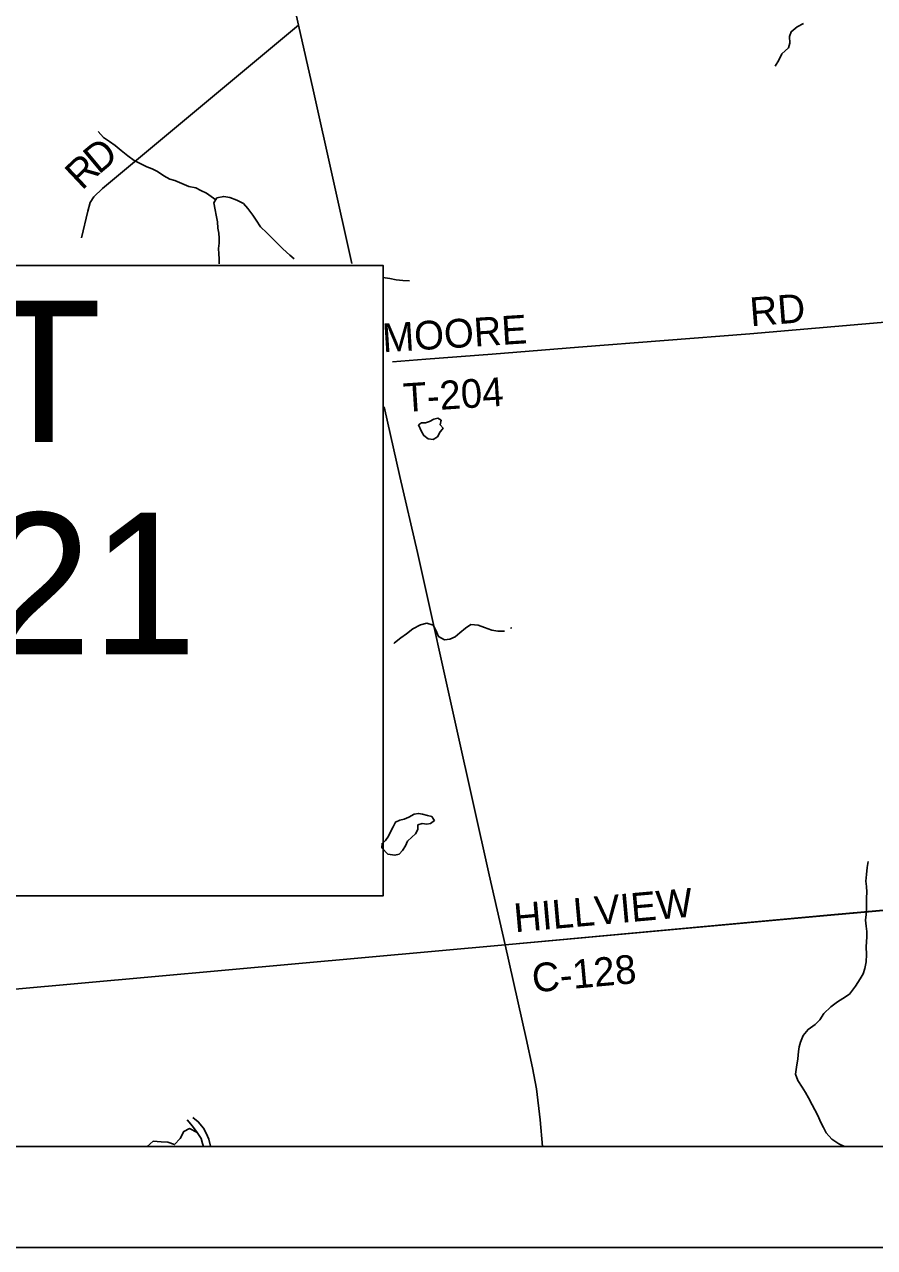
# Model space of a CAD drawing. Extents: x 0 to 34, y 0 to 22.
# Drawn here: x 6.665 to 7.506, y 14 to 15.21 of the extents above; entities that cross this region are included whole.
import ezdxf

# ---------------------------------------------------------------- set-up
doc = ezdxf.new("R2010")
doc.units = 0
for name, color, linetype in [('GM_X_Corporation', 7, 'Continuous'), ('GM_X_County_Road', 7, 'Continuous'), ('GM_X_County_Road_Text', 7, 'Continuous'), ('GM_X_Minor_Lake', 7, 'Continuous'), ('GM_X_Minor_River', 7, 'Continuous'), ('GM_X_State_Route', 7, 'Continuous'), ('GM_X_Township_Road', 7, 'Continuous'), ('GM_X_Township_Road_Text', 7, 'Continuous'), ('SH_Data', 7, 'Continuous'), ('SH_Text', 7, 'Continuous')]:
    doc.layers.add(name, color=color, linetype=linetype)

msp = doc.modelspace()

# ---------------------------------------------------------------- linework, layer by layer
at = {"layer": 'GM_X_Corporation'}
msp.add_lwpolyline([(2.7052, 14.1), (8.9, 14.1), (8.9, 20.9), (3.3687, 20.9)], dxfattribs=at)
msp.add_lwpolyline([(5.0367, 14.1), (8.579, 14.1), (8.5781, 14.1185), (8.5553, 14.4065), (8.4217, 14.3956), (8.2117, 14.3797), (8.0986, 14.3711), (7.9912, 14.363), (7.8543, 14.3535), (7.661, 14.3447), (7.5929, 14.3405), (7.4631, 14.3291), (7.1407, 14.2995), (6.5134, 14.2426), (6.0344, 14.1984), (5.9982, 14.195), (5.4229, 14.1455), (5.0357, 14.1114)], close=True, dxfattribs=at)
at = {"layer": 'GM_X_County_Road'}
for points in [[(6.7214, 14.9988), (6.7276, 15.0252), (6.7301, 15.0337), (6.7336, 15.0395), (6.7423, 15.0475), (6.9363, 15.2093)], [(7.1408, 14.2993), (7.4632, 14.3289), (7.593, 14.3402), (7.6611, 14.3445), (7.8544, 14.3533), (7.9913, 14.3627)]]:
    msp.add_lwpolyline(points, dxfattribs=at)
at = {"layer": 'GM_X_Minor_Lake'}
for points in [[(7.0783, 14.8092), (7.0793, 14.8107), (7.0765, 14.814), (7.0774, 14.8183), (7.0742, 14.8204), (7.0702, 14.8193), (7.066, 14.8172), (7.0621, 14.8157), (7.0579, 14.8159), (7.055, 14.8137)], [(7.055, 14.8137), (7.0579, 14.8072), (7.0603, 14.8032), (7.0647, 14.8), (7.0696, 14.7994), (7.0738, 14.802), (7.0766, 14.8068), (7.0783, 14.8092)], [(7.07, 14.4238), (7.0682, 14.4264), (7.0638, 14.4274), (7.0591, 14.4286), (7.0549, 14.4295), (7.0506, 14.4286), (7.0456, 14.4258), (7.0407, 14.4237), (7.0367, 14.4229), (7.0324, 14.4209), (7.0299, 14.4163), (7.0276, 14.412), (7.0253, 14.4069), (7.0223, 14.4027), (7.019, 14.3997), (7.0186, 14.3953), (7.0247, 14.3891)], [(7.0247, 14.3891), (7.0317, 14.3881), (7.0358, 14.389), (7.0393, 14.3928), (7.0423, 14.3975), (7.044, 14.4021), (7.0484, 14.4058), (7.0522, 14.4092), (7.0545, 14.4136), (7.0545, 14.4181), (7.0587, 14.4196), (7.0632, 14.4189), (7.067, 14.4196), (7.0708, 14.4226), (7.07, 14.4238)]]:
    msp.add_lwpolyline(points, dxfattribs=at)
at = {"layer": 'GM_X_Minor_River'}
for points in [[(7.436, 15.2108), (7.4297, 15.2076), (7.4238, 15.2027), (7.4221, 15.198), (7.4225, 15.1915), (7.4211, 15.1868), (7.4148, 15.1809), (7.4116, 15.1747), (7.408, 15.1688)], [(6.8543, 15.0364), (6.8451, 15.0429), (6.8395, 15.0456), (6.8346, 15.0483), (6.8276, 15.0497), (6.8208, 15.0526), (6.814, 15.0556), (6.809, 15.057), (6.803, 15.0603), (6.7966, 15.0643), (6.7913, 15.067), (6.786, 15.0691), (6.7796, 15.0725), (6.7737, 15.0752), (6.7675, 15.08), (6.7607, 15.0852), (6.7547, 15.0903), (6.7492, 15.0941), (6.7433, 15.098), (6.7381, 15.1041)], [(6.8577, 14.9732), (6.8579, 14.978), (6.8575, 14.9829), (6.8572, 14.9882), (6.8578, 14.9934), (6.8578, 14.9985), (6.8574, 15.0034), (6.8565, 15.0085), (6.856, 15.0148), (6.8547, 15.0213), (6.8538, 15.0264), (6.8525, 15.0334), (6.8555, 15.0383), (6.8622, 15.0398), (6.8684, 15.0386), (6.8752, 15.0361), (6.8818, 15.0327), (6.886, 15.0277), (6.8911, 15.0211), (6.8944, 15.0163), (6.8988, 15.0098), (6.905, 15.0037), (6.9095, 14.999), (6.9148, 14.994), (6.9208, 14.9881), (6.9278, 14.9816), (6.932, 14.9781)], [(7.0197, 14.9596), (7.0267, 14.9585), (7.033, 14.9573), (7.0394, 14.9565), (7.046, 14.9563)], [(7.0307, 14.5974), (7.0314, 14.5982), (7.0377, 14.6031), (7.0432, 14.607), (7.0495, 14.6119), (7.0569, 14.6161), (7.0633, 14.6177), (7.0696, 14.6156), (7.0722, 14.6107), (7.0748, 14.6044), (7.0809, 14.6011), (7.086, 14.6017), (7.0913, 14.6041), (7.0961, 14.6081), (7.1016, 14.6126), (7.1067, 14.6162), (7.1141, 14.6156), (7.1205, 14.6132), (7.1275, 14.6107), (7.1336, 14.6096), (7.14, 14.6097)], [(7.146, 14.6128), (7.1475, 14.6129)], [(7.4765, 14.1), (7.4709, 14.1025), (7.4641, 14.1073), (7.4585, 14.1136), (7.456, 14.1189), (7.453, 14.1242), (7.4506, 14.1299), (7.4472, 14.1362), (7.4446, 14.1413), (7.441, 14.1482), (7.438, 14.1533), (7.4346, 14.1586), (7.4306, 14.1651), (7.4282, 14.1716), (7.429, 14.1784), (7.4305, 14.1867), (7.4311, 14.1938), (7.4319, 14.1985), (7.4332, 14.2032), (7.4359, 14.2097), (7.4407, 14.2157), (7.4475, 14.2206), (7.4523, 14.2252), (7.4561, 14.2316), (7.463, 14.2382), (7.4696, 14.243), (7.4751, 14.2462), (7.4816, 14.2507), (7.4875, 14.2584), (7.4923, 14.2658), (7.4951, 14.2707), (7.4968, 14.2759), (7.4982, 14.2827), (7.4984, 14.2899), (7.4981, 14.2975), (7.4983, 14.3024), (7.4989, 14.3074), (7.4989, 14.3125), (7.498, 14.3178), (7.4974, 14.3239), (7.498, 14.3294), (7.4986, 14.3362), (7.4986, 14.3413), (7.4985, 14.3461), (7.4987, 14.3516), (7.4983, 14.3571), (7.4979, 14.3624), (7.4985, 14.369), (7.4991, 14.3759), (7.5001, 14.3819)], [(6.8261, 14.1263), (6.8312, 14.1202), (6.8359, 14.1139), (6.8398, 14.1077), (6.8413, 14.1029), (6.8422, 14.1)], [(6.8494, 14.1), (6.8492, 14.1004), (6.8476, 14.1072), (6.8448, 14.1131), (6.8421, 14.1181), (6.8371, 14.1244), (6.8318, 14.1287)], [(6.8359, 14.1138), (6.8285, 14.1176), (6.8228, 14.1148), (6.8192, 14.108), (6.8136, 14.1019), (6.807, 14.1042), (6.8004, 14.1046), (6.7923, 14.1051), (6.7864, 14.1)]]:
    msp.add_lwpolyline(points, dxfattribs=at)
at = {"layer": 'GM_X_State_Route'}
for points in [[(6.9891, 14.9735), (6.9507, 15.1451), (6.9363, 15.2093), (6.9181, 15.2908), (6.8946, 15.3945)], [(7.1408, 14.2993), (7.1251, 14.3688), (7.0934, 14.5108), (7.0539, 14.6877), (7.0365, 14.7626), (7.0212, 14.8318)], [(7.1778, 14.1), (7.1755, 14.1263), (7.1717, 14.157), (7.168, 14.1778), (7.1615, 14.2068), (7.1408, 14.2993)]]:
    msp.add_lwpolyline(points, dxfattribs=at)
at = {"layer": 'GM_X_Township_Road'}
msp.add_lwpolyline([(7.0294, 14.8761), (7.0624, 14.8787), (7.1278, 14.8838), (7.2135, 14.8907), (7.3829, 14.9039), (7.5131, 14.915), (7.5926, 14.9225), (7.8221, 14.9464)], dxfattribs=at)
at = {"layer": 'SH_Data'}
for p, q in [((2.1, 14.1), (8.9, 14.1)), ((2, 14), (9, 14))]:
    msp.add_line(p, q, dxfattribs=at)
at = {"layer": 'SH_Text'}
msp.add_lwpolyline([(5.1971, 14.9716), (7.0199, 14.9716), (7.0199, 14.3479), (5.1971, 14.3479)], close=True, dxfattribs=at)

# ---------------------------------------------------------------- texts
at = {"layer": 'GM_X_County_Road_Text'}
for s, height, rotation, p in [('D', 0.0284, 39.8051, (6.7385, 15.0609)), ('R', 0.0284, 43.4184, (6.7219, 15.0452)), ('HILLVIEW', 0.02841, 5.0795, (7.1506, 14.3118)), ('C-128', 0.02841, 5.2446, (7.1686, 14.2523))]:
    msp.add_text(s, height=height, rotation=rotation, dxfattribs=at).set_placement(p)
at = {"layer": 'GM_X_Township_Road_Text'}
for s, rotation, p in [('RD', 4.4743, (7.384, 14.9113)), ('MOORE', 3.612, (7.02, 14.8855)), ('T-204', 3.6464, (7.0409, 14.8264))]:
    msp.add_text(s, height=0.02841, rotation=rotation, dxfattribs=at).set_placement(p)
at = {"layer": 'SH_Text'}
for s, p in [('BEGIN PROJECT  ', (5.2331, 14.7968)), ('UNI-739, SLM 6.21 ', (5.2331, 14.5868))]:
    msp.add_text(s, height=0.14, dxfattribs=at).set_placement(p)

doc.saveas('drawing.dxf')
